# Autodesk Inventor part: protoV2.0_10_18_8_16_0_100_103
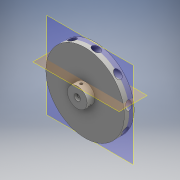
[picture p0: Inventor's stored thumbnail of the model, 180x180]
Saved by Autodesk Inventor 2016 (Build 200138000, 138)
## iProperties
Created: 2016-09
Part Number: protoV2.0_10_18_8_16_0_100_103
Material: Generic
Document SubType Name: Modeling
Designer: Matt&Celia
Density: 1 g/cm^3
Appearance: Default
Author: Matt&Celia
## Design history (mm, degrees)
sketch "Sketch1"
  geometry: C1 r 100 at (0, 0); 1 further point
  constraints: 1 centre point, 1 coincident
  dimensions: "d0" = 200 diameter of C1
extrude "Extrusion1" new body sketch "Sketch1" distance "d1" = 25; taper "d2" = 0 deg
workplane "Work Plane1"
sketch "Sketch2"
  geometry: L1 (0, 0)-(0, 70); L2 (0, 70)-(-71.414, 70); L3 (-62.578, 78)-(-22.578, 78); L4 (-28.924, 70)-(-28.924, 78); L5 (-22.578, 62)-(-78.46, 62); L6 (-78.46, 62)-(-78.46, 70); L7 (-78.46, 70)-(-22.578, 70); L8 (-22.578, 70)-(-22.578, 62); C1 r 30 at (0, 0); A1 r 100 centre (0, 0) between (-71.414, 70) and (-62.578, 78) reference
  constraints: 16 end point, 3 point on circle, 3 point on line, 2 horizontal, 2 parallel, 2 perpendicular, 2 vertical, 1 centre point, 1 coincident, 1 collinear
  dimensions: "d3" = 70 distance of L1.start L1.end; "d8" = 40 distance of L3.start L3.end; "d9" = 8 distance of L4.start L4.end; "d11" = 8 distance of L5.end L6.end; "d16" = 60 diameter of C1
revolve "Revolution1" sketch "Sketch2" stored, may be unused: angle "d12" = 90 deg
pattern_circular "Circular Pattern1" dims angle "d14" = 360 deg
sketch "Sketch6"
  geometry: C1 r 25 at (0, 0); 1 further point
  constraints: 1 centre point, 1 coincident
  dimensions: "d18" = 50 diameter of C1
extrude "Extrusion2" join sketch "Sketch6" distance "d19" = 20; taper "d20" = 0 deg
mirror "Mirror3"
sketch "Sketch7"
  geometry: 1 further point
hole "Hole1" sketch "Sketch7" at (0, 0) diameter "d21" = 16; stored, may be unused: countersink angle "d25" = 82 deg, drill point angle "d27" = 118 deg; dims "d22" = 6, "d23" = 9.779, "d24" = 2, "d26" = 8.8
workplane "Work Plane4"
sketch "Sketch11"
  geometry: L1 (-25, -20)-(25, -20) reference; L2 (-100, 0)-(100, 0) reference; 2 further points
  dimensions: "d28" = 10 distance from line of L1 point (0, -10) (= 0.5 x d29); "d29" = 20 distance between parallel lines of L2 L1 (derived)
hole "Hole2" sketch "Sketch11" at (0, -10) diameter "d30" = 6.647; stored, may be unused: countersink angle "d34" = 82 deg, drill point angle "d36" = 118 deg; dims "d31" = 18, "d32" = 9.779, "d33" = 2, "d35" = 18
pattern_circular "Circular Pattern2" dims angle "d38" = 360 deg
mirror "Mirror4"
body "Solid1"
